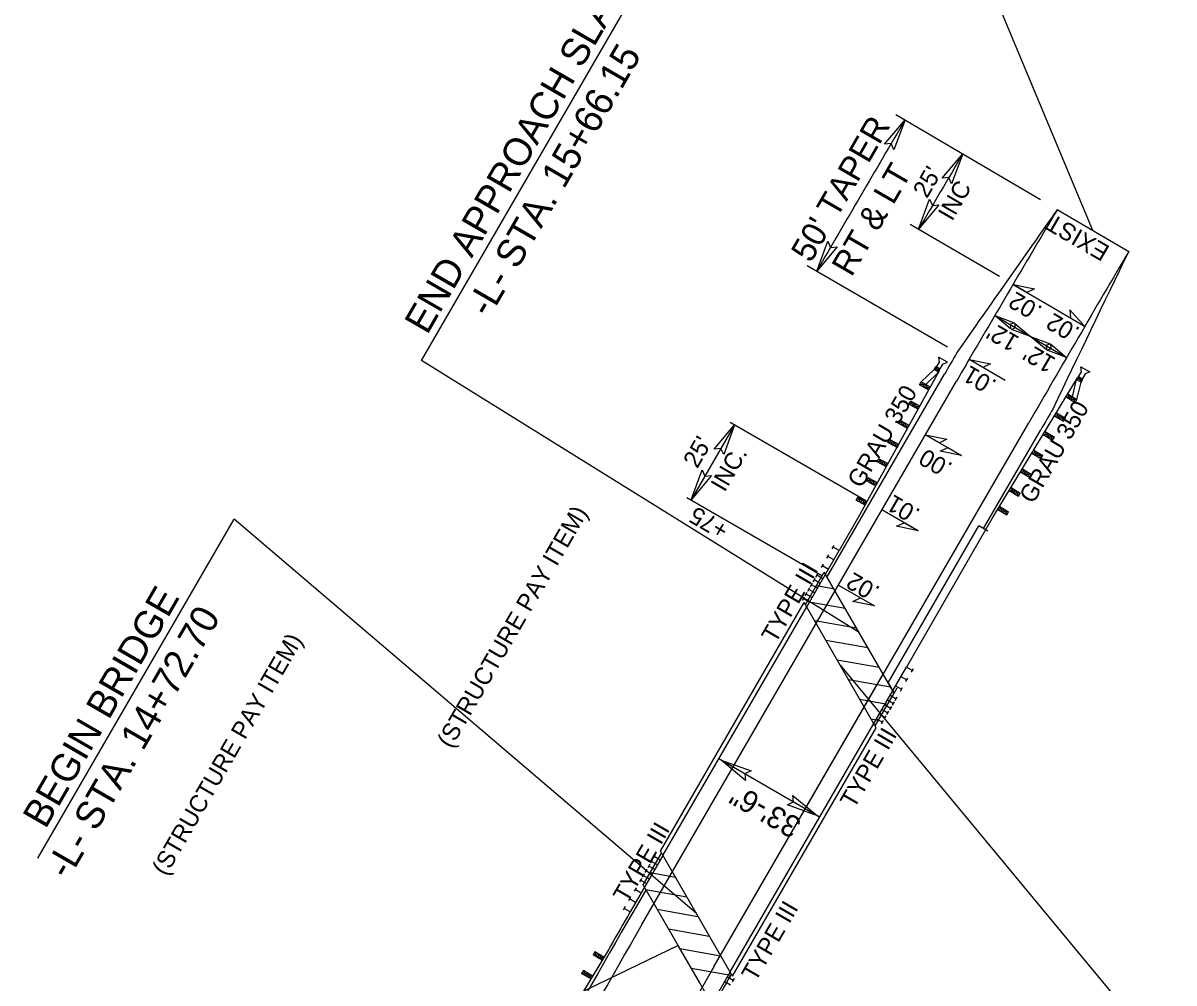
# Model space of a CAD drawing. Extents: x 1653308 to 1654073, y 597542 to 598622.
# Drawn here: x 1653543.1 to 1653874.2, y 597977.2 to 598253.5 of the extents above; entities that cross this region are included whole.
import ezdxf

# ---------------------------------------------------------------- set-up
doc = ezdxf.new("R2010")
doc.units = 0
for name, color, linetype in [('Default', 7, 'Continuous'), ('Prop Approach Slab', 7, 'Continuous'), ('Prop Approach Slab Hatching', 7, 'Continuous'), ('Prop Dimension', 7, 'Continuous'), ('Prop Dimension Text', 7, 'Continuous'), ('Prop EOT', 7, 'Continuous'), ('Prop Guardrail', 7, 'Continuous'), ('Prop Guardrail Anchor Unit CELL', 7, 'Continuous'), ('Prop Paved Shoulder', 7, 'Continuous'), ('Prop Roadway Bridge', 7, 'Continuous'), ('Prop SBG', 7, 'Continuous'), ('Prop Structure Anchor Unit CELL', 7, 'Continuous'), ('Prop Superelevation  Arrow CELL', 7, 'Continuous'), ('Prop Superelevation Label', 7, 'Continuous'), ('Prop Terminator CELL', 7, 'Continuous')]:
    doc.layers.add(name, color=color, linetype=linetype)

msp = doc.modelspace()

# ---------------------------------------------------------------- linework, layer by layer
at = {"layer": 'Default'}
for p, q in [((1653820.68, 598107.28), (1653818.08, 598108.79)), ((1653791.95, 598063.63), (1653793.68, 598060.63)), ((1653793.7, 598060.6), (1653794.57, 598062.11))]:
    msp.add_line(p, q, dxfattribs=at)
at = {"layer": 'Prop Approach Slab'}
for p, q in [((1653768.17, 598086.09), (1653773.61, 598095.48)), ((1653793.68, 598060.63), (1653773.61, 598095.48)), ((1653788.59, 598050.65), (1653767.84, 598086.67)), ((1653788.25, 598051.24), (1653793.68, 598060.63)), ((1653721.52, 598005.47), (1653726.8, 598014.59)), ((1653747.22, 597979.16), (1653726.47, 598015.18)), ((1653741.61, 597970.59), (1653721.52, 598005.47)), ((1653737.78, 597977.24), (1653731.56, 597988.04)), ((1653746.64, 597979.32), (1653746.88, 597979.74))]:
    msp.add_line(p, q, dxfattribs=at)
msp.add_arc((1655696.35, 596851.16), 2252.58, 149.9451, 150.2012, dxfattribs=at)
at = {"layer": 'Prop Approach Slab Hatching'}
for p, q in [((1653771.36, 598091.6), (1653776.12, 598090.75)), ((1653768.69, 598086.99), (1653779.61, 598085.05)), ((1653770.86, 598081.53), (1653782.87, 598079.39)), ((1653774.09, 598075.88), (1653786.13, 598073.74)), ((1653777.32, 598070.22), (1653789.39, 598068.08)), ((1653780.55, 598064.57), (1653792.65, 598062.42)), ((1653783.77, 598058.92), (1653791.87, 598057.48)), ((1653787, 598053.27), (1653789.2, 598052.88)), ((1653723.55, 598008.98), (1653730.86, 598007.68)), ((1653722.3, 598004.12), (1653734.07, 598002.03)), ((1653725.56, 597998.46), (1653737.29, 597996.38)), ((1653728.82, 597992.81), (1653740.51, 597990.73)), ((1653732.08, 597987.15), (1653743.73, 597985.08)), ((1653735.34, 597981.49), (1653746.72, 597979.47))]:
    msp.add_line(p, q, dxfattribs=at)
at = {"layer": 'Prop Dimension'}
for p, q in [((1653850.86, 598193.8), (1653755.08, 598422.92)), ((1653657.71, 598156.32), (1653729.38, 598280.07)), ((1653794.16, 598227.15), (1653835.86, 598202.63)), ((1653824.06, 598180.51), (1653798.35, 598195.52)), ((1653809.1, 598160.22), (1653768.73, 598183.63)), ((1653822.65, 598169.26), (1653832.98, 598163.25)), ((1653832.98, 598163.25), (1653843.3, 598157.24)), ((1653783.64, 598078.05), (1653657.71, 598156.32)), ((1653747.84, 598137.88), (1653735.32, 598116.24)), ((1653746.59, 598138.6), (1653785.58, 598116.04)), ((1653734.07, 598116.96), (1653773.06, 598094.4)), ((1653547.35, 598013.14), (1653603.86, 598110.72)), ((1653736.84, 597997.17), (1653603.86, 598110.72)), ((1653778.21, 598068.66), (1653874.22, 597952.72)), ((1653772.28, 598024.97), (1653743.29, 598041.75)), ((1653731.56, 597988.04), (1653575.7, 597912.69))]:
    msp.add_line(p, q, dxfattribs=at)
for radius, end in [(8062.65, 149.893623), (8043.4, 149.714573)]:
    msp.add_arc((1660746.41, 594137.77), radius, 149.535524, end, dxfattribs=at)
at = {"layer": 'Prop EOT'}
for p, q in [((1653840.66, 598199.8), (1653861.19, 598187.72)), ((1653721.18, 597994.05), (1653811.65, 598150.42)), ((1653741.95, 597982.03), (1653832.43, 598138.4)), ((1653741.95, 597982.03), (1653790.56, 598066.05))]:
    msp.add_line(p, q, dxfattribs=at)
for centre, radius, start, end in [((1660732.42, 594113.82), 8011.96, 149.337203, 149.694767), ((1660747.27, 594139.24), 7988.01, 149.547734, 149.957313), ((1660746.41, 594137.77), 8012, 149.893089, 149.945103), ((1655696.35, 596851.16), 2282, 149.9451, 155.30659), ((1655696.35, 596851.16), 2258, 149.9451, 155.29325)]:
    msp.add_arc(centre, radius, start, end, dxfattribs=at)
at = {"layer": 'Prop Guardrail'}
for p, q in [((1653784.18, 598112.48), (1653777.93, 598101.66)), ((1653822.25, 598111.44), (1653797.24, 598068.14)), ((1653717.8, 597997.7), (1653717.06, 597996.43))]:
    msp.add_line(p, q, dxfattribs=at)
msp.add_arc((1655696.35, 596851.16), 2286.75, 149.9451, 150.2237, dxfattribs=at)
at = {"layer": 'Prop Guardrail Anchor Unit CELL'}
for p, q in [((1653809.05, 598155.86), (1653806.5, 598157.32)), ((1653806.5, 598157.32), (1653806.66, 598155.88)), ((1653801.46, 598150.18), (1653805.19, 598153.71)), ((1653805.19, 598153.71), (1653805.68, 598154.59)), ((1653805.19, 598153.71), (1653805.44, 598154.15)), ((1653806.99, 598153.87), (1653805.19, 598153.71)), ((1653806.51, 598152.99), (1653805.19, 598153.71)), ((1653806.66, 598155.88), (1653805.64, 598154.1)), ((1653805.64, 598154.1), (1653806.17, 598153.8)), ((1653806.99, 598153.87), (1653805.68, 598154.59)), ((1653805.68, 598154.59), (1653806.51, 598152.99)), ((1653806.17, 598153.8), (1653806.7, 598153.49)), ((1653806.7, 598153.49), (1653807.72, 598155.27)), ((1653807.72, 598155.27), (1653809.05, 598155.86)), ((1653847.58, 598153.09), (1653847.43, 598154.53)), ((1653847.43, 598154.53), (1653849.97, 598153.06)), ((1653784.18, 598112.48), (1653806.75, 598153.43)), ((1653802.8, 598149.44), (1653806.51, 598152.99)), ((1653822.25, 598111.34), (1653846.47, 598151.33)), ((1653844.99, 598145.91), (1653846.21, 598150.9)), ((1653848.02, 598150.98), (1653846.21, 598150.9)), ((1653846.21, 598150.9), (1653847.5, 598150.12)), ((1653846.55, 598151.32), (1653847.58, 598153.09)), ((1653847.08, 598151.01), (1653846.55, 598151.32)), ((1653846.73, 598151.76), (1653848.02, 598150.98)), ((1653846.73, 598151.76), (1653847.5, 598150.12)), ((1653847.61, 598150.7), (1653847.08, 598151.01)), ((1653847.5, 598150.12), (1653848.02, 598150.98)), ((1653847.5, 598150.12), (1653847.76, 598150.55)), ((1653848.64, 598152.47), (1653847.61, 598150.7)), ((1653849.97, 598153.06), (1653848.64, 598152.47)), ((1653800.98, 598149.3), (1653801.46, 598150.18)), ((1653802.8, 598149.44), (1653800.98, 598149.3)), ((1653803.66, 598147.82), (1653800.98, 598149.3)), ((1653804.14, 598148.7), (1653801.46, 598150.18)), ((1653801.46, 598150.18), (1653802.32, 598148.56)), ((1653802.32, 598148.56), (1653802.8, 598149.44)), ((1653802.32, 598148.56), (1653804.14, 598148.7)), ((1653803.66, 598147.82), (1653802.8, 598149.44)), ((1653846.3, 598145.12), (1653847.5, 598150.12)), ((1653797.99, 598143.75), (1653798.47, 598144.63)), ((1653799.79, 598143.9), (1653797.99, 598143.75)), ((1653800.62, 598142.3), (1653797.99, 598143.75)), ((1653801.1, 598143.18), (1653798.47, 598144.63)), ((1653798.47, 598144.63), (1653799.3, 598143.03)), ((1653799.3, 598143.03), (1653799.79, 598143.9)), ((1653800.62, 598142.3), (1653799.79, 598143.9)), ((1653843.16, 598145.85), (1653844.99, 598145.91)), ((1653843.16, 598145.85), (1653845.78, 598144.27)), ((1653843.68, 598146.71), (1653846.3, 598145.12)), ((1653844.47, 598145.06), (1653843.68, 598146.71)), ((1653844.47, 598145.06), (1653844.99, 598145.91)), ((1653846.3, 598145.12), (1653844.47, 598145.06)), ((1653844.99, 598145.91), (1653845.78, 598144.27)), ((1653845.78, 598144.27), (1653846.3, 598145.12)), ((1653799.3, 598143.03), (1653801.1, 598143.18)), ((1653839.89, 598140.46), (1653841.69, 598140.54)), ((1653839.89, 598140.46), (1653842.46, 598138.91)), ((1653840.41, 598141.32), (1653842.98, 598139.76)), ((1653841.18, 598139.69), (1653840.41, 598141.32)), ((1653841.18, 598139.69), (1653841.69, 598140.54)), ((1653841.69, 598140.54), (1653842.46, 598138.91)), ((1653794.83, 598138.3), (1653795.31, 598139.17)), ((1653796.69, 598138.42), (1653794.83, 598138.3)), ((1653797.58, 598136.78), (1653794.83, 598138.3)), ((1653798.06, 598137.66), (1653795.31, 598139.17)), ((1653795.31, 598139.17), (1653796.2, 598137.54)), ((1653796.2, 598137.54), (1653796.69, 598138.42)), ((1653796.2, 598137.54), (1653798.06, 598137.66)), ((1653797.58, 598136.78), (1653796.69, 598138.42)), ((1653842.98, 598139.76), (1653841.18, 598139.69)), ((1653842.46, 598138.91), (1653842.98, 598139.76)), ((1653836.63, 598135.07), (1653838.49, 598135.11)), ((1653836.63, 598135.07), (1653839.31, 598133.45)), ((1653837.15, 598135.93), (1653839.83, 598134.3)), ((1653837.97, 598134.26), (1653837.15, 598135.93)), ((1653837.97, 598134.26), (1653838.49, 598135.11)), ((1653839.83, 598134.3), (1653837.97, 598134.26)), ((1653838.49, 598135.11), (1653839.31, 598133.45)), ((1653839.31, 598133.45), (1653839.83, 598134.3)), ((1653791.88, 598132.73), (1653792.36, 598133.61)), ((1653793.69, 598132.87), (1653791.88, 598132.73)), ((1653794.54, 598131.27), (1653791.88, 598132.73)), ((1653795.02, 598132.14), (1653792.36, 598133.61)), ((1653792.36, 598133.61), (1653793.21, 598132)), ((1653793.21, 598132), (1653793.69, 598132.87)), ((1653793.21, 598132), (1653795.02, 598132.14)), ((1653794.54, 598131.27), (1653793.69, 598132.87)), ((1653794.54, 598131.27), (1653795.02, 598132.14)), ((1653833.36, 598129.68), (1653833.88, 598130.54)), ((1653833.88, 598130.54), (1653836.48, 598128.97)), ((1653834.66, 598128.9), (1653833.88, 598130.54)), ((1653788.82, 598127.22), (1653789.31, 598128.09)), ((1653790.64, 598127.36), (1653788.82, 598127.22)), ((1653791.49, 598125.75), (1653788.82, 598127.22)), ((1653791.98, 598126.62), (1653789.31, 598128.09)), ((1653789.31, 598128.09), (1653790.16, 598126.48)), ((1653790.16, 598126.48), (1653790.64, 598127.36)), ((1653791.49, 598125.75), (1653790.64, 598127.36)), ((1653833.36, 598129.68), (1653835.18, 598129.75)), ((1653833.36, 598129.68), (1653835.96, 598128.11)), ((1653834.66, 598128.9), (1653835.18, 598129.75)), ((1653836.48, 598128.97), (1653834.66, 598128.9)), ((1653835.18, 598129.75), (1653835.96, 598128.11)), ((1653835.96, 598128.11), (1653836.48, 598128.97)), ((1653790.16, 598126.48), (1653791.98, 598126.62)), ((1653830.1, 598124.29), (1653831.92, 598124.36)), ((1653830.1, 598124.29), (1653832.71, 598122.71)), ((1653830.62, 598125.15), (1653833.22, 598123.57)), ((1653831.4, 598123.5), (1653830.62, 598125.15)), ((1653831.4, 598123.5), (1653831.92, 598124.36)), ((1653831.92, 598124.36), (1653832.71, 598122.71)), ((1653785.78, 598121.7), (1653786.26, 598122.58)), ((1653787.6, 598121.84), (1653785.78, 598121.7)), ((1653788.45, 598120.23), (1653785.78, 598121.7)), ((1653788.94, 598121.1), (1653786.26, 598122.58)), ((1653786.26, 598122.58), (1653787.12, 598120.97)), ((1653787.12, 598120.97), (1653787.6, 598121.84)), ((1653787.12, 598120.97), (1653788.94, 598121.1)), ((1653788.45, 598120.23), (1653787.6, 598121.84)), ((1653833.22, 598123.57), (1653831.4, 598123.5)), ((1653832.71, 598122.71), (1653833.22, 598123.57)), ((1653826.84, 598118.9), (1653828.66, 598118.97)), ((1653826.84, 598118.9), (1653829.45, 598117.32)), ((1653827.35, 598119.76), (1653829.96, 598118.18)), ((1653828.14, 598118.11), (1653827.35, 598119.76)), ((1653828.14, 598118.11), (1653828.66, 598118.97)), ((1653829.96, 598118.18), (1653828.14, 598118.11)), ((1653828.66, 598118.97), (1653829.45, 598117.32)), ((1653829.45, 598117.32), (1653829.96, 598118.18)), ((1653782.78, 598116.16), (1653783.27, 598117.03)), ((1653784.58, 598116.31), (1653782.78, 598116.16)), ((1653785.41, 598114.71), (1653782.78, 598116.16)), ((1653785.89, 598115.59), (1653783.27, 598117.03)), ((1653783.27, 598117.03), (1653784.1, 598115.43)), ((1653784.1, 598115.43), (1653784.58, 598116.31)), ((1653784.1, 598115.43), (1653785.89, 598115.59)), ((1653785.89, 598115.59), (1653784.58, 598116.31)), ((1653784.58, 598116.31), (1653785.41, 598114.71)), ((1653785.41, 598114.71), (1653785.89, 598115.59)), ((1653823.57, 598113.51), (1653824.09, 598114.37)), ((1653824.09, 598114.37), (1653826.65, 598112.81)), ((1653824.09, 598114.37), (1653825.37, 598113.59)), ((1653824.85, 598112.74), (1653824.09, 598114.37)), ((1653825.37, 598113.59), (1653823.57, 598113.51)), ((1653823.57, 598113.51), (1653826.14, 598111.96)), ((1653824.85, 598112.74), (1653825.37, 598113.59)), ((1653826.65, 598112.81), (1653824.85, 598112.74)), ((1653825.37, 598113.59), (1653826.14, 598111.96)), ((1653826.14, 598111.96), (1653826.65, 598112.81)), ((1653711.52, 597986.79), (1653687.3, 597946.81)), ((1653707.64, 597986.17), (1653707.12, 597985.32)), ((1653707.12, 597985.32), (1653708.92, 597985.4)), ((1653709.68, 597983.76), (1653707.12, 597985.32)), ((1653710.2, 597984.62), (1653707.64, 597986.17)), ((1653708.4, 597984.54), (1653707.64, 597986.17)), ((1653708.92, 597985.4), (1653708.4, 597984.54)), ((1653708.92, 597985.4), (1653709.68, 597983.76)), ((1653708.4, 597984.54), (1653710.2, 597984.62)), ((1653709.68, 597983.76), (1653708.4, 597984.54)), ((1653710.2, 597984.62), (1653709.68, 597983.76)), ((1653704.33, 597980.81), (1653703.81, 597979.96)), ((1653703.81, 597979.96), (1653705.63, 597980.02)), ((1653706.42, 597978.37), (1653703.81, 597979.96)), ((1653706.94, 597979.23), (1653704.33, 597980.81)), ((1653705.11, 597979.16), (1653704.33, 597980.81)), ((1653705.63, 597980.02), (1653705.11, 597979.16)), ((1653706.94, 597979.23), (1653705.11, 597979.16)), ((1653705.63, 597980.02), (1653706.42, 597978.37))]:
    msp.add_line(p, q, dxfattribs=at)
at = {"layer": 'Prop Paved Shoulder'}
for p, q in [((1653774.42, 598094.06), (1653808.19, 598152.42)), ((1653819.45, 598107.99), (1653835.89, 598136.39))]:
    msp.add_line(p, q, dxfattribs=at)
for centre, radius, start, end in [((1660410.84, 593559.18), 8043.79, 144.765822, 145.123297), ((1661067.71, 594691.93), 8009.65, 154.122498, 154.481227), ((1660746.41, 594137.77), 8016, 149.893089, 149.945103), ((1660746.41, 594137.77), 7984, 149.894163, 149.945103), ((1655696.35, 596851.16), 2286, 149.71581, 155.30659)]:
    msp.add_arc(centre, radius, start, end, dxfattribs=at)
at = {"layer": 'Prop Roadway Bridge'}
for p, q in [((1653726.47, 598015.18), (1653767.84, 598086.67)), ((1653727.19, 598013.93), (1653768.56, 598085.42)), ((1653746.5, 597980.41), (1653787.87, 598051.9)), ((1653747.22, 597979.16), (1653788.59, 598050.65))]:
    msp.add_line(p, q, dxfattribs=at)
at = {"layer": 'Prop SBG'}
msp.add_line((1653791.95, 598063.63), (1653818.08, 598108.79), dxfattribs=at)
at = {"layer": 'Prop Structure Anchor Unit CELL'}
for p, q in [((1653768.56, 598085.42), (1653777.93, 598101.66)), ((1653775.91, 598102.16), (1653776.49, 598103.15)), ((1653777.93, 598101.66), (1653776.2, 598102.66)), ((1653772.79, 598096.75), (1653773.36, 598097.74)), ((1653774.35, 598099.46), (1653774.92, 598100.45)), ((1653776.37, 598098.95), (1653774.64, 598099.95)), ((1653771.23, 598094.04), (1653771.8, 598095.04)), ((1653773.24, 598093.54), (1653771.51, 598094.54)), ((1653774.81, 598096.25), (1653773.08, 598097.25)), ((1653768.88, 598089.98), (1653769.45, 598090.98)), ((1653769.66, 598091.34), (1653770.24, 598092.33)), ((1653771.68, 598090.83), (1653769.95, 598091.83)), ((1653770.44, 598092.69), (1653771.02, 598093.68)), ((1653772.46, 598092.19), (1653770.73, 598093.19)), ((1653767.32, 598087.28), (1653767.89, 598088.27)), ((1653769.34, 598086.77), (1653767.61, 598087.77)), ((1653768.1, 598088.63), (1653768.67, 598089.62)), ((1653770.12, 598088.13), (1653768.39, 598089.13)), ((1653770.9, 598089.48), (1653769.17, 598090.48)), ((1653787.87, 598051.9), (1653797.24, 598068.14)), ((1653797.24, 598068.14), (1653798.97, 598067.14)), ((1653798.69, 598066.64), (1653799.26, 598067.64)), ((1653795.68, 598065.43), (1653797.41, 598064.43)), ((1653797.12, 598063.94), (1653797.7, 598064.93)), ((1653794.12, 598062.73), (1653795.85, 598061.73)), ((1653795.56, 598061.23), (1653796.13, 598062.22)), ((1653791.77, 598058.67), (1653793.5, 598057.67)), ((1653792.55, 598060.02), (1653794.29, 598059.02)), ((1653793.22, 598057.17), (1653793.79, 598058.16)), ((1653794, 598058.53), (1653794.57, 598059.52)), ((1653789.43, 598054.61), (1653791.16, 598053.61)), ((1653790.21, 598055.96), (1653791.94, 598054.96)), ((1653790.99, 598057.32), (1653792.72, 598056.31)), ((1653791.66, 598054.47), (1653792.23, 598055.46)), ((1653792.44, 598055.82), (1653793.01, 598056.81)), ((1653788.65, 598053.26), (1653790.38, 598052.26)), ((1653790.09, 598051.76), (1653790.67, 598052.75)), ((1653790.87, 598053.11), (1653791.45, 598054.1)), ((1653727.19, 598013.93), (1653717.8, 597997.7)), ((1653723.4, 598011.37), (1653722.82, 598010.38)), ((1653724.18, 598012.72), (1653723.6, 598011.73)), ((1653725.62, 598011.22), (1653723.89, 598012.22)), ((1653724.96, 598014.07), (1653724.39, 598013.08)), ((1653726.41, 598012.57), (1653724.67, 598013.58)), ((1653721.83, 598008.66), (1653721.26, 598007.67)), ((1653723.28, 598007.17), (1653721.54, 598008.17)), ((1653722.61, 598010.01), (1653722.04, 598009.02)), ((1653724.06, 598008.52), (1653722.33, 598009.52)), ((1653724.84, 598009.87), (1653723.11, 598010.87)), ((1653721.05, 598007.31), (1653720.47, 598006.32)), ((1653722.49, 598005.81), (1653720.76, 598006.81)), ((1653717.92, 598001.9), (1653717.34, 598000.91)), ((1653719.36, 598000.4), (1653717.63, 598001.4)), ((1653719.48, 598004.61), (1653718.91, 598003.61)), ((1653720.93, 598003.11), (1653719.2, 598004.11)), ((1653716.35, 597999.2), (1653715.78, 597998.2)), ((1653717.8, 597997.7), (1653716.07, 597998.7)), ((1653746.5, 597980.41), (1653737.11, 597964.18)), ((1653745.71, 597979.06), (1653747.45, 597978.05)), ((1653747.73, 597978.55), (1653747.16, 597977.56)), ((1653744.93, 597977.7), (1653746.66, 597976.7))]:
    msp.add_line(p, q, dxfattribs=at)
at = {"layer": 'Prop Superelevation  Arrow CELL'}
for points in [[(1653827.93, 598178.24), (1653834.12, 598176.95), (1653831.92, 598175.91)], [(1653848.5, 598166.23), (1653844.3, 598170.95), (1653844.49, 598168.53)], [(1653815.26, 598156.65), (1653821.45, 598155.35), (1653819.26, 598154.32)], [(1653802.73, 598135), (1653808.92, 598133.71), (1653806.73, 598132.67)], [(1653813.12, 598128.99), (1653806.92, 598130.26), (1653809.12, 598131.31)], [(1653800.6, 598107.35), (1653794.4, 598108.63), (1653796.59, 598109.67)], [(1653788.08, 598085.71), (1653781.88, 598086.99), (1653784.07, 598088.03)]]:
    msp.add_lwpolyline(points, close=True, dxfattribs=at)
at = {"layer": 'Prop Superelevation Label'}
for p, q in [((1653827.93, 598178.24), (1653838.22, 598172.24)), ((1653838.22, 598172.24), (1653848.5, 598166.23)), ((1653825.64, 598150.63), (1653815.26, 598156.65)), ((1653802.73, 598135), (1653813.12, 598128.99)), ((1653800.6, 598107.35), (1653790.21, 598113.36)), ((1653777.69, 598091.72), (1653788.08, 598085.71))]:
    msp.add_line(p, q, dxfattribs=at)
at = {"layer": 'Prop Terminator CELL'}
for points in [[(1653790.96, 598218.59), (1653796.86, 598225.57), (1653793.65, 598216.95), (1653792.86, 598218.75)], [(1653807.55, 598208.83), (1653813.45, 598215.81), (1653810.24, 598207.19), (1653809.45, 598209)], [(1653806.62, 598201.11), (1653800.74, 598194.12), (1653803.92, 598202.74), (1653804.73, 598200.94)], [(1653777.31, 598189.06), (1653771.45, 598182.05), (1653774.61, 598190.68), (1653775.41, 598188.88)], [(1653827.19, 598165.45), (1653822.65, 598169.26), (1653828.25, 598167.2), (1653827.08, 598166.68)], [(1653828.48, 598167.02), (1653832.98, 598163.25), (1653827.43, 598165.29), (1653828.59, 598165.81)], [(1653837.52, 598159.44), (1653832.98, 598163.25), (1653838.58, 598161.19), (1653837.41, 598160.67)], [(1653838.8, 598161.01), (1653843.3, 598157.24), (1653837.76, 598159.28), (1653838.91, 598159.79)], [(1653741.99, 598130.87), (1653747.84, 598137.88), (1653744.69, 598129.25), (1653743.88, 598131.04)], [(1653741.17, 598123.25), (1653735.32, 598116.24), (1653738.47, 598124.88), (1653739.28, 598123.08)], [(1653750.95, 598035.53), (1653743.94, 598041.38), (1653752.57, 598038.23), (1653750.78, 598037.42)], [(1653764.62, 598031.2), (1653771.63, 598025.35), (1653763, 598028.5), (1653764.8, 598029.31)]]:
    msp.add_lwpolyline(points, close=True, dxfattribs=at)

# ---------------------------------------------------------------- texts
at = {"layer": 'Default'}
for p in [(1653666.28, 598044.48), (1653584.28, 598007.77)]:
    msp.add_text('(STRUCTURE PAY ITEM)', height=5, rotation=59.9255, dxfattribs=at).set_placement(p)
at = {"layer": 'Prop Dimension'}
for s, height, rotation, p in [("12'", 5.103, 149.7891, (1653830.04, 598162.94)), ("12'", 5.103, 149.7891, (1653840.54, 598156.82)), ('33\'-6"', 6.3, 149.9451, (1653767.49, 598024))]:
    msp.add_text(s, height=height, rotation=rotation, dxfattribs=at).set_placement(p)
at = {"layer": 'Prop Dimension Text'}
for s, height, rotation, p in [('END APPROACH SLAB', 8, 59.9255, (1653659.4, 598163.5)), ('-L- STA. 15+66.15', 8, 59.9255, (1653677.25, 598168.39)), ("50' TAPER", 7, 59.9255, (1653769.75, 598184.19)), ('RT & LT', 7, 59.9255, (1653781.45, 598180.15)), ("25'", 5, 59.9255, (1653803.16, 598202.76)), ('INC', 5, 59.9255, (1653810.37, 598196.23)), ("25'", 5, 59.9255, (1653737.08, 598125.05)), ('INC.', 5, 59.9255, (1653744.97, 598118.24)), ('+75', 5, 149.9451, (1653746.55, 598108.86)), ('BEGIN BRIDGE', 8, 59.9255, (1653549.6, 598021.3)), ('-L- STA. 14+72.70', 8, 59.9255, (1653556.16, 598006.68))]:
    msp.add_text(s, height=height, rotation=rotation, dxfattribs=at).set_placement(p)
at = {"layer": 'Prop Guardrail Anchor Unit CELL'}
for p in [(1653784.32, 598119.33), (1653833.74, 598114.85)]:
    msp.add_text('GRAU 350', height=5, rotation=59.9255, dxfattribs=at).set_placement(p)
at = {"layer": 'Prop Structure Anchor Unit CELL'}
for p in [(1653759.6, 598074.7), (1653782.22, 598027.16), (1653716.92, 597999.97), (1653753.86, 597977.33)]:
    msp.add_text('TYPE III', height=5, rotation=59.9255, dxfattribs=at).set_placement(p)
at = {"layer": 'Prop Superelevation Label'}
for s, rotation, p in [('EXIST', 149.752, (1653856.08, 598189)), ('.02', 149.755, (1653836.68, 598171.67)), ('.02', 149.755, (1653847.5, 598165.54)), ('.01', 149.755, (1653823.54, 598150.39)), ('.00', 149.9451, (1653810.87, 598126.53)), ('.01', 149.9451, (1653801.59, 598113.27)), ('.02', 149.9451, (1653789.98, 598090.95))]:
    msp.add_text(s, height=5, rotation=rotation, dxfattribs=at).set_placement(p)

doc.saveas('drawing.dxf')
